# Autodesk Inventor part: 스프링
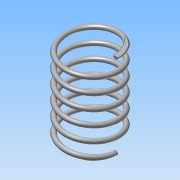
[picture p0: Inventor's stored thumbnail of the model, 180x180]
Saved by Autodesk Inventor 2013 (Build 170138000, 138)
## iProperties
Created: 2018-06
Part Number: 스프링
Material: 강철, 연강
Document SubType Name: Modeling
Designer: Administrator
Density: 7.86 g/cm^3
Mass: 82.8071 g
Surface Area: 106.473 cm^2
Volume: 10.5353 cm^3
Author: Administrator
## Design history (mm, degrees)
sketch "스케치1"
  geometry: L1 (0, 0)-(0, 73.25); L2 (0, 0)-(22.5, 0); L3 (0, 73.25)-(22.5, 73.25); C1 r 2 at (22.5, 0)
  constraints: 6 end point, 1 centre point, 1 coincident, 1 perpendicular, 1 vertical
  dimensions: "d0" = 73.25 distance of L1.start L1.end (derived); "d1" = 22.5 distance of L1.start L2.end; "d2" = 4 diameter of C1; "d3" = 22.5 distance of L1.end L3.end
feature "코일1" sketch "스케치1" pitch "d4" = 10; turns "d6" = 6; dims "d5" = 73.25 (= d0), "d7" = 0, angle "d8" = 90 deg, angle "d9" = 90 deg, "d10" = 0, "d11" = 0
sketch "스케치2"
  geometry: L1 (73.25, 25)-(0, 25); L2 (0, 25)-(0, -25); L3 (0, -25)-(73.25, -25); L4 (73.25, -25)-(73.25, 25); 2 further points
  constraints: 8 end point, 2 parallel, 1 coincident, 1 horizontal, 1 midpoint, 1 perpendicular
  dimensions: "d12" = 73.25 distance of L2.end L3.end (derived); "d14" = 50 distance of L3.end L1.start
extrude "돌출1" sketch "스케치2" stored distance "d15" = 10; taper "d16" = 0 deg
node "솔리드1"
